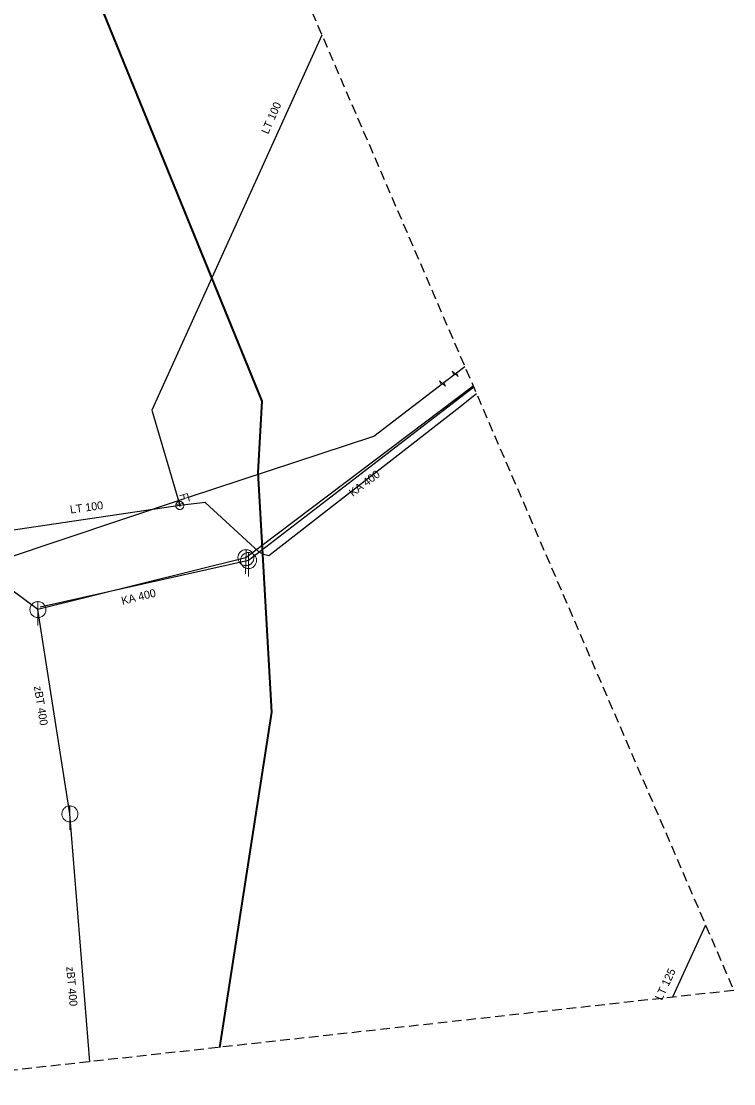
# Model space of a CAD drawing. Extents: x -774415 to -774100, y -975744 to -975502.
# Drawn here: x -774189.4 to -774100.4, y -975744.3 to -975611.6 of the extents above; entities that cross this region are included whole.
import ezdxf

# ---------------------------------------------------------------- set-up
doc = ezdxf.new("R2010")
doc.units = 0
doc.header["$LTSCALE"] = 0.4
doc.linetypes.add('MEDIUM_DASHED', pattern=[4.5, 3, -1.5])
for name, color, linetype, lineweight in [('1', 7, 'MEDIUM_DASHED', 25), ('14', 7, 'Continuous', 13), ('17', 7, 'Continuous', 25), ('22', 7, 'Continuous', 13), ('34', 7, 'Continuous', 13), ('47', 7, 'Continuous', 13)]:
    doc.layers.add(name, color=color, linetype=linetype, lineweight=lineweight)

msp = doc.modelspace()

# ---------------------------------------------------------------- linework, layer by layer
at = {"layer": '1'}
msp.add_lwpolyline([(-774414.714, -975561.823), (-774378.138, -975501.935), (-774197.267, -975507.964), (-774100.401, -975732.645), (-774205.708, -975744.301), (-774260.773, -975651.856)], close=True, dxfattribs=at)
at = {"layer": '14', "lineweight": 25}
for p, q in [((-774132.929, -975657.196), (-774161.329, -975678.6)), ((-774132.879, -975657.313), (-774161.008, -975678.956)), ((-774187.309, -975685.09), (-774207.107, -975670.35)), ((-774161.329, -975678.6), (-774187.309, -975685.09)), ((-774161.008, -975678.956), (-774187.033, -975684.781)), ((-774183.316, -975710.609), (-774187.309, -975685.09)), ((-774180.839, -975741.549), (-774183.316, -975710.609))]:
    msp.add_line(p, q, dxfattribs=at)
at = {"layer": '14'}
for p, q in [((-774169.134, -975670.732), (-774168.992, -975671.211)), ((-774168.992, -975671.211), (-774168.517, -975671.054)), ((-774169.59, -975672.079), (-774169.614, -975671.905))]:
    msp.add_line(p, q, dxfattribs=at)
at = {"layer": '17'}
for p, q in [((-774135.188, -975655.627), (-774133.999, -975654.715)), ((-774136.776, -975656.844), (-774135.188, -975655.627)), ((-774103.913, -975724.5), (-774108.056, -975733.493))]:
    msp.add_line(p, q, dxfattribs=at)
at = {"layer": '17', "lineweight": 35}
msp.add_lwpolyline([(-774217.009, -975507.306), (-774211.739, -975524.879), (-774208.02, -975534.129), (-774200.302, -975558.73), (-774159.333, -975659.052), (-774159.853, -975667.971), (-774158.147, -975697.895), (-774164.627, -975739.754)], dxfattribs=at)
at = {"layer": '17'}
for points in [[(-774151.837, -975613.338), (-774173.098, -975660.18), (-774169.614, -975671.905)], [(-774205.166, -975638.503), (-774202.903, -975645.324), (-774191.719, -975678.835), (-774168.992, -975671.211)], [(-774168.517, -975671.054), (-774145.34, -975663.409), (-774136.776, -975656.844)], [(-774132.516, -975658.154), (-774134.969, -975660.079), (-774158.46, -975678.37), (-774159.14, -975678.219), (-774159.699, -975677.89), (-774166.44, -975671.69), (-774169.59, -975672.079), (-774190.649, -975675.19)]]:
    msp.add_lwpolyline(points, dxfattribs=at)
at = {"layer": '22'}
for p, q in [((-774161.369, -975680.6), (-774161.308, -975677.6)), ((-774161.008, -975680.956), (-774161.007, -975677.956)), ((-774187.309, -975687.09), (-774187.308, -975684.09)), ((-774183.316, -975712.609), (-774183.315, -975709.609))]:
    msp.add_line(p, q, dxfattribs=at)
for points in [[(-774160.329, -975678.62), (-774160.333, -975678.511), (-774160.348, -975678.403), (-774160.376, -975678.296), (-774160.414, -975678.194), (-774160.464, -975678.096), (-774160.524, -975678.005), (-774160.595, -975677.921), (-774160.673, -975677.845), (-774160.76, -975677.777), (-774160.853, -975677.72), (-774160.952, -975677.673), (-774161.056, -975677.638), (-774161.163, -975677.614), (-774161.271, -975677.602), (-774161.381, -975677.602), (-774161.49, -975677.614), (-774161.597, -975677.636), (-774161.701, -975677.671), (-774161.8, -975677.718), (-774161.893, -975677.774), (-774161.98, -975677.842), (-774162.059, -975677.917), (-774162.13, -975678.002), (-774162.19, -975678.093), (-774162.24, -975678.19), (-774162.279, -975678.292), (-774162.308, -975678.398), (-774162.324, -975678.506), (-774162.328, -975678.616), (-774162.32, -975678.725), (-774162.301, -975678.832), (-774162.27, -975678.937), (-774162.228, -975679.038), (-774162.174, -975679.134), (-774162.11, -975679.223), (-774162.038, -975679.305), (-774161.956, -975679.378), (-774161.868, -975679.442), (-774161.773, -975679.496), (-774161.672, -975679.539), (-774161.567, -975679.571), (-774161.46, -975679.592), (-774161.35, -975679.6), (-774161.241, -975679.596), (-774161.132, -975679.58), (-774161.027, -975679.553), (-774160.924, -975679.514), (-774160.826, -975679.464), (-774160.735, -975679.404), (-774160.65, -975679.335), (-774160.574, -975679.256), (-774160.507, -975679.17), (-774160.449, -975679.077), (-774160.403, -975678.978), (-774160.367, -975678.874), (-774160.343, -975678.767), (-774160.33, -975678.658)], [(-774160.008, -975678.956), (-774160.013, -975678.847), (-774160.031, -975678.739), (-774160.061, -975678.633), (-774160.101, -975678.532), (-774160.153, -975678.435), (-774160.215, -975678.345), (-774160.287, -975678.262), (-774160.367, -975678.188), (-774160.455, -975678.122), (-774160.549, -975678.067), (-774160.649, -975678.022), (-774160.754, -975677.989), (-774160.861, -975677.967), (-774160.97, -975677.957), (-774161.08, -975677.959), (-774161.188, -975677.973), (-774161.295, -975677.998), (-774161.398, -975678.035), (-774161.496, -975678.084), (-774161.588, -975678.142), (-774161.674, -975678.211), (-774161.751, -975678.288), (-774161.82, -975678.374), (-774161.879, -975678.466), (-774161.927, -975678.564), (-774161.964, -975678.667), (-774161.99, -975678.774), (-774162.004, -975678.882), (-774162.007, -975678.992), (-774161.997, -975679.101), (-774161.976, -975679.208), (-774161.942, -975679.312), (-774161.898, -975679.412), (-774161.843, -975679.507), (-774161.777, -975679.595), (-774161.703, -975679.675), (-774161.62, -975679.747), (-774161.53, -975679.809), (-774161.434, -975679.861), (-774161.332, -975679.902), (-774161.227, -975679.932), (-774161.119, -975679.95), (-774161.009, -975679.956), (-774160.9, -975679.95), (-774160.792, -975679.932), (-774160.687, -975679.903), (-774160.585, -975679.862), (-774160.488, -975679.81), (-774160.398, -975679.748), (-774160.315, -975679.677), (-774160.24, -975679.597), (-774160.175, -975679.509), (-774160.119, -975679.415), (-774160.075, -975679.315), (-774160.041, -975679.211), (-774160.019, -975679.103), (-774160.009, -975678.994)], [(-774186.309, -975685.09), (-774186.314, -975684.981), (-774186.332, -975684.873), (-774186.362, -975684.767), (-774186.402, -975684.666), (-774186.454, -975684.569), (-774186.516, -975684.479), (-774186.588, -975684.396), (-774186.668, -975684.322), (-774186.756, -975684.256), (-774186.85, -975684.201), (-774186.95, -975684.156), (-774187.055, -975684.123), (-774187.162, -975684.101), (-774187.271, -975684.091), (-774187.381, -975684.093), (-774187.489, -975684.107), (-774187.596, -975684.132), (-774187.699, -975684.169), (-774187.797, -975684.218), (-774187.889, -975684.276), (-774187.975, -975684.345), (-774188.052, -975684.422), (-774188.121, -975684.508), (-774188.18, -975684.6), (-774188.228, -975684.698), (-774188.265, -975684.801), (-774188.291, -975684.908), (-774188.305, -975685.016), (-774188.308, -975685.126), (-774188.298, -975685.235), (-774188.277, -975685.342), (-774188.243, -975685.446), (-774188.199, -975685.546), (-774188.144, -975685.641), (-774188.078, -975685.729), (-774188.004, -975685.809), (-774187.921, -975685.881), (-774187.831, -975685.943), (-774187.735, -975685.995), (-774187.633, -975686.036), (-774187.528, -975686.066), (-774187.42, -975686.084), (-774187.31, -975686.09), (-774187.201, -975686.084), (-774187.093, -975686.066), (-774186.988, -975686.037), (-774186.886, -975685.996), (-774186.789, -975685.944), (-774186.699, -975685.882), (-774186.616, -975685.811), (-774186.541, -975685.731), (-774186.476, -975685.643), (-774186.42, -975685.549), (-774186.376, -975685.449), (-774186.342, -975685.345), (-774186.32, -975685.237), (-774186.31, -975685.128)], [(-774182.316, -975710.609), (-774182.321, -975710.5), (-774182.339, -975710.392), (-774182.369, -975710.286), (-774182.409, -975710.185), (-774182.461, -975710.088), (-774182.523, -975709.998), (-774182.595, -975709.915), (-774182.675, -975709.841), (-774182.763, -975709.775), (-774182.857, -975709.72), (-774182.957, -975709.675), (-774183.062, -975709.642), (-774183.169, -975709.62), (-774183.278, -975709.61), (-774183.388, -975709.612), (-774183.496, -975709.626), (-774183.603, -975709.651), (-774183.706, -975709.688), (-774183.804, -975709.737), (-774183.896, -975709.795), (-774183.982, -975709.864), (-774184.059, -975709.941), (-774184.128, -975710.027), (-774184.187, -975710.119), (-774184.235, -975710.217), (-774184.272, -975710.32), (-774184.298, -975710.427), (-774184.312, -975710.535), (-774184.315, -975710.645), (-774184.305, -975710.754), (-774184.284, -975710.861), (-774184.25, -975710.965), (-774184.206, -975711.065), (-774184.151, -975711.16), (-774184.085, -975711.248), (-774184.011, -975711.328), (-774183.928, -975711.4), (-774183.838, -975711.462), (-774183.742, -975711.514), (-774183.64, -975711.555), (-774183.535, -975711.585), (-774183.427, -975711.603), (-774183.317, -975711.609), (-774183.208, -975711.603), (-774183.1, -975711.585), (-774182.995, -975711.556), (-774182.893, -975711.515), (-774182.796, -975711.463), (-774182.706, -975711.401), (-774182.623, -975711.33), (-774182.548, -975711.25), (-774182.483, -975711.162), (-774182.427, -975711.068), (-774182.383, -975710.968), (-774182.349, -975710.864), (-774182.327, -975710.756), (-774182.317, -975710.647)]]:
    msp.add_lwpolyline(points, close=True, dxfattribs=at)
at = {"layer": '34'}
for p, q in [((-774168.654, -975670.589), (-774169.613, -975670.873)), ((-774168.674, -975670.579), (-774168.36, -975671.528)), ((-774170.109, -975671.973), (-774169.118, -975671.837))]:
    msp.add_line(p, q, dxfattribs=at)
at = {"layer": '47'}
for p, q in [((-774135.569, -975655.289), (-774135.347, -975655.749)), ((-774137.157, -975656.506), (-774136.935, -975656.966))]:
    msp.add_line(p, q, dxfattribs=at)
for points in [[(-774135.569, -975655.289), (-774134.806, -975655.964), (-774135.028, -975655.504)], [(-774137.157, -975656.506), (-774136.394, -975657.181), (-774136.616, -975656.721)]]:
    msp.add_lwpolyline(points, dxfattribs=at)
for points in [[(-774169.383, -975671.623), (-774169.431, -975671.604), (-774169.482, -975671.59), (-774169.533, -975671.582), (-774169.585, -975671.578), (-774169.638, -975671.581), (-774169.69, -975671.589), (-774169.74, -975671.603), (-774169.789, -975671.621), (-774169.836, -975671.644), (-774169.88, -975671.672), (-774169.922, -975671.705), (-774169.958, -975671.742), (-774169.992, -975671.782), (-774170.021, -975671.826), (-774170.045, -975671.872), (-774170.064, -975671.92), (-774170.078, -975671.971), (-774170.086, -975672.023), (-774170.09, -975672.074), (-774170.087, -975672.127), (-774170.079, -975672.179), (-774170.066, -975672.23), (-774170.047, -975672.279), (-774170.025, -975672.326), (-774169.996, -975672.369), (-774169.963, -975672.411), (-774169.927, -975672.448), (-774169.886, -975672.481), (-774169.842, -975672.51), (-774169.796, -975672.534), (-774169.748, -975672.553), (-774169.697, -975672.567), (-774169.645, -975672.576), (-774169.594, -975672.579), (-774169.541, -975672.576), (-774169.489, -975672.569), (-774169.438, -975672.556), (-774169.389, -975672.537), (-774169.342, -975672.514), (-774169.299, -975672.485), (-774169.257, -975672.452), (-774169.22, -975672.416), (-774169.187, -975672.375), (-774169.158, -975672.331), (-774169.134, -975672.285), (-774169.115, -975672.237), (-774169.101, -975672.186), (-774169.092, -975672.135), (-774169.089, -975672.083), (-774169.092, -975672.03), (-774169.099, -975671.978), (-774169.113, -975671.928), (-774169.131, -975671.879), (-774169.155, -975671.832), (-774169.183, -975671.788), (-774169.216, -975671.746), (-774169.252, -975671.71), (-774169.293, -975671.676), (-774169.337, -975671.647)], [(-774169.556, -975672.004), (-774169.564, -975672), (-774169.572, -975671.999), (-774169.58, -975671.997), (-774169.589, -975671.997), (-774169.597, -975671.997), (-774169.606, -975671.999), (-774169.614, -975672), (-774169.622, -975672.003), (-774169.63, -975672.008), (-774169.637, -975672.012), (-774169.644, -975672.017), (-774169.65, -975672.023), (-774169.655, -975672.03), (-774169.66, -975672.036), (-774169.664, -975672.045), (-774169.668, -975672.053), (-774169.669, -975672.061), (-774169.671, -975672.069), (-774169.671, -975672.078), (-774169.671, -975672.086), (-774169.669, -975672.095), (-774169.668, -975672.103), (-774169.665, -975672.111), (-774169.661, -975672.12), (-774169.656, -975672.126), (-774169.651, -975672.133), (-774169.645, -975672.139), (-774169.638, -975672.144), (-774169.632, -975672.149), (-774169.623, -975672.153), (-774169.615, -975672.157), (-774169.607, -975672.158), (-774169.599, -975672.16), (-774169.59, -975672.16), (-774169.582, -975672.16), (-774169.573, -975672.159), (-774169.565, -975672.157), (-774169.557, -975672.154), (-774169.548, -975672.15), (-774169.542, -975672.145), (-774169.535, -975672.14), (-774169.529, -975672.134), (-774169.524, -975672.127), (-774169.519, -975672.121), (-774169.515, -975672.112), (-774169.511, -975672.104), (-774169.51, -975672.096), (-774169.508, -975672.088), (-774169.508, -975672.079), (-774169.508, -975672.071), (-774169.509, -975672.062), (-774169.511, -975672.054), (-774169.514, -975672.046), (-774169.519, -975672.038), (-774169.523, -975672.031), (-774169.528, -975672.024), (-774169.534, -975672.018), (-774169.541, -975672.013), (-774169.547, -975672.008)]]:
    msp.add_lwpolyline(points, close=True, dxfattribs=at)

# ---------------------------------------------------------------- texts
at = {"layer": '1'}
for s, rotation, p in [('LT 100', 66, (-774158.566, -975625.781)), ('KA 400', 37, (-774147.98, -975671.025)), ('LT 100', 8, (-774183.231, -975673.097)), ('KA 400', 14, (-774176.749, -975684.498)), ('zBT 400 ', 279, (-774187.815, -975694.698)), ('zBT 400 ', 275, (-774183.779, -975729.695)), ('LT 125', 65, (-774109.377, -975733.964))]:
    msp.add_text(s, height=1, rotation=rotation, dxfattribs=at).set_placement(p)

doc.saveas('drawing.dxf')
